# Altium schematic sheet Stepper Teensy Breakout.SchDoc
size A4
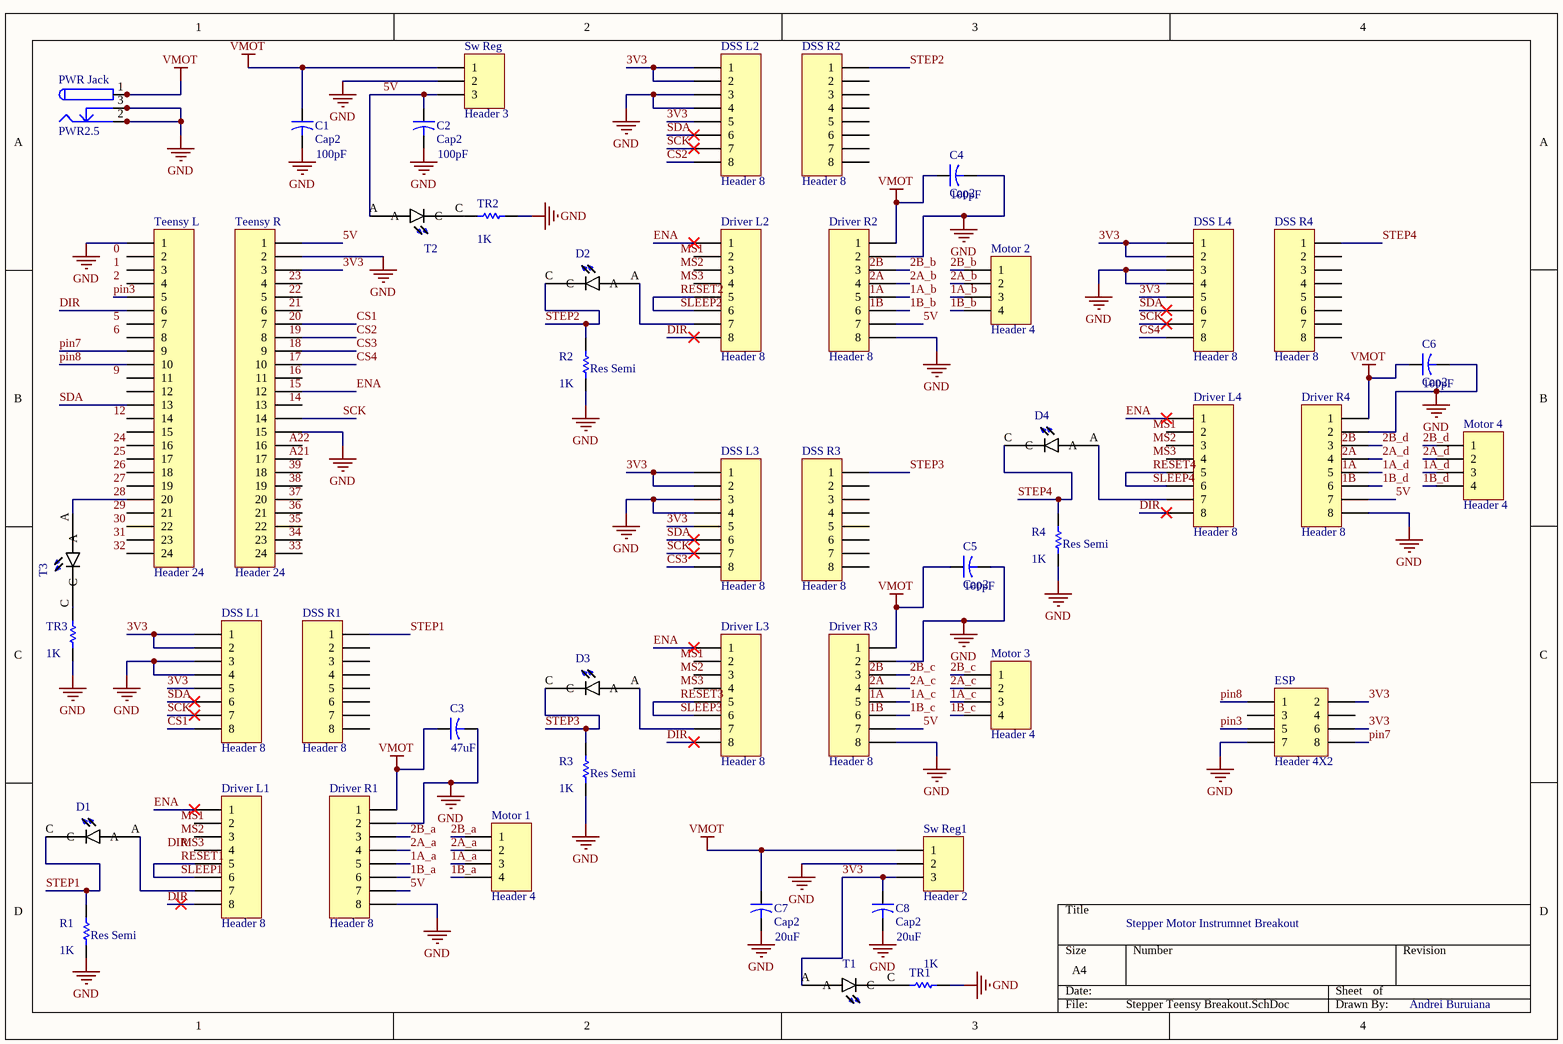
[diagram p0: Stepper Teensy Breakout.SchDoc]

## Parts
C1  Cap2  value 100pF  [CAPR5-4X5]
C2  Cap2  value 100pF  [CAPR5-4X5]
C3  value 47uF  [CAPR5-4X5]
C4  Cap2  value 100pF  [CAPR5-4X5]
C5  Cap2  value 100pF  [CAPR5-4X5]
C6  Cap2  value 100pF  [CAPR5-4X5]
C7  Cap2  value 20uF  [CAPR5-4X5]
C8  Cap2  value 20uF  [CAPR5-4X5]
D1  LTL-1CHYE  [LED_LTL-1CHYE_LTL-1CHYE(Primary)]  (value not drawn)
D2  LTL-1CHYE  [LED_LTL-1CHYE_LTL-1CHYE(Primary)]  (value not drawn)
D3  LTL-1CHYE  [LED_LTL-1CHYE_LTL-1CHYE(Primary)]  (value not drawn)
D4  LTL-1CHYE  [LED_LTL-1CHYE_LTL-1CHYE(Primary)]  (value not drawn)
Driver_L1  Header 8  [HDR1X8]
Driver_L2  Header 8  [HDR1X8]
Driver_L3  Header 8  [HDR1X8]
Driver_L4  Header 8  [HDR1X8]
Driver_R1  Header 8  [HDR1X8]
Driver_R2  Header 8  [HDR1X8]
Driver_R3  Header 8  [HDR1X8]
Driver_R4  Header 8  [HDR1X8]
DSS_L1  Header 8  [HDR1X8]
DSS_L2  Header 8  [HDR1X8]
DSS_L3  Header 8  [HDR1X8]
DSS_L4  Header 8  [HDR1X8]
DSS_R1  Header 8  [HDR1X8]
DSS_R2  Header 8  [HDR1X8]
DSS_R3  Header 8  [HDR1X8]
DSS_R4  Header 8  [HDR1X8]
ESP  Header 4X2  [HDR2X4]
Motor_1  Header 4  [HDR1X4]
Motor_2  Header 4  [HDR1X4]
Motor_3  Header 4  [HDR1X4]
Motor_4  Header 4  [HDR1X4]
PWR_Jack  PWR2.5  [KLD-0202]
R1  Res Semi  value 1K  [AXIAL-0.5]
R2  Res Semi  value 1K  [AXIAL-0.5]
R3  Res Semi  value 1K  [AXIAL-0.5]
R4  Res Semi  value 1K  [AXIAL-0.5]
Sw_Reg  Header 3  [HDR1X3]
Sw_Reg1  Header 2  [HDR1X3]
T1  LTL-1CHYE  [LED_LTL-1CHYE_LTL-1CHYE(Primary)]  (value not drawn)
T2  LTL-1CHYE  [LED_LTL-1CHYE_LTL-1CHYE(Primary)]  (value not drawn)
T3  LTL-1CHYE  [LED_LTL-1CHYE_LTL-1CHYE(Primary)]  (value not drawn)
Teensy_L  Header 24  [HDR1X24]
Teensy_R  Header 24  [HDR1X24]
TR1  value 1K  [AXIAL-0.5]
TR2  value 1K  [AXIAL-0.5]
TR3  value 1K  [AXIAL-0.5]

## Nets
GND: C1.2 C2.2 C3.2 C4.2 C5.2 C6.2 C7.2 C8.2 Driver_R1.2 Driver_R1.8 Driver_R2.2 Driver_R2.8 Driver_R3.2 Driver_R3.8 Driver_R4.2 Driver_R4.8 DSS_L1.3 DSS_L1.4 DSS_L2.3 DSS_L2.4 DSS_L3.3 DSS_L3.4 DSS_L4.3 DSS_L4.4 ESP.7 PWR_Jack.2 PWR_Jack.2A PWR_Jack.2B PWR_Jack.3 PWR_Jack.3A PWR_Jack.3B R1.1 R2.1 R3.1 R4.1 Sw_Reg.2 Sw_Reg1.2 Teensy_L.1 Teensy_R.2 Teensy_R.15 TR1.1 TR2.1 TR3.1
VMOT: C1.1 C3.1 C4.1 C5.1 C6.1 C7.1 Driver_R1.1 Driver_R2.1 Driver_R3.1 Driver_R4.1 PWR_Jack.1 PWR_Jack.1A PWR_Jack.1B Sw_Reg.1 Sw_Reg1.1
1A_a: Driver_R1.5 Motor_1.3
1A_b: Driver_R2.5 Motor_2.3
1A_c: Driver_R3.5 Motor_3.3
1A_d: Driver_R4.5 Motor_4.3
1B_a: Driver_R1.6 Motor_1.4
1B_b: Driver_R2.6 Motor_2.4
1B_c: Driver_R3.6 Motor_3.4
1B_d: Driver_R4.6 Motor_4.4
2A_a: Driver_R1.4 Motor_1.2
2A_b: Driver_R2.4 Motor_2.2
2A_c: Driver_R3.4 Motor_3.2
2A_d: Driver_R4.4 Motor_4.2
2B_a: Driver_R1.3 Motor_1.1
2B_b: Driver_R2.3 Motor_2.1
2B_c: Driver_R3.3 Motor_3.1
2B_d: Driver_R4.3 Motor_4.1
3V3: C8.1 DSS_L1.1 DSS_L1.2 DSS_L1.5 DSS_L2.1 DSS_L2.2 DSS_L2.5 DSS_L3.1 DSS_L3.2 DSS_L3.5 DSS_L4.1 DSS_L4.2 DSS_L4.5 ESP.2 ESP.6 Sw_Reg1.3 T1.A Teensy_R.3
5V: C2.1 Driver_R1.7 Driver_R2.7 Driver_R3.7 Driver_R4.7 Sw_Reg.3 T2.A Teensy_R.1
28: T3.A Teensy_L.20
CS1: DSS_L1.8 Teensy_R.7
CS2: DSS_L2.8 Teensy_R.8
CS3: DSS_L3.8 Teensy_R.9
CS4: DSS_L4.8 Teensy_R.10
DIR: Driver_L1.8 Driver_L2.8 Driver_L3.8 Driver_L4.8 Teensy_L.6
ENA: Driver_L1.1 Driver_L2.1 Driver_L3.1 Driver_L4.1 Teensy_R.12
pin3: ESP.5 Teensy_L.5
pin7: ESP.8 Teensy_L.9
pin8: ESP.1 Teensy_L.10
RESET1: Driver_L1.5 Driver_L1.6  [also labelled SLEEP1]
RESET2: Driver_L2.5 Driver_L2.6  [also labelled SLEEP2]
RESET3: Driver_L3.5 Driver_L3.6  [also labelled SLEEP3]
RESET4: Driver_L4.5 Driver_L4.6  [also labelled SLEEP4]
SCK: DSS_L1.7 DSS_L2.7 DSS_L3.7 DSS_L4.7 Teensy_R.14
SDA: DSS_L1.6 DSS_L2.6 DSS_L3.6 DSS_L4.6 Teensy_L.13
STEP1: D1.C DSS_R1.1 R1.2
STEP2: D2.C DSS_R2.1 R2.2
STEP3: D3.C DSS_R3.1 R3.2
STEP4: D4.C DSS_R4.1 R4.2
NetD1_A: D1.A Driver_L1.7
NetD2_A: D2.A Driver_L2.7
NetD3_A: D3.A Driver_L3.7
NetD4_A: D4.A Driver_L4.7
NetT1_C: T1.C TR1.2
NetT2_C: T2.C TR2.2
NetT3_C: T3.C TR3.2

Not connected (* = marked no-connect by the designer): Driver_L1 2 3 4; Driver_L2 2 3 4; Driver_L3 2 3 4; Driver_L4 2 3 4; DSS_R1 2 3 4 5 6 7 8; DSS_R2 2 3 4 5 6 7 8; DSS_R3 2 3 4 5 6 7 8; DSS_R4 2 3 4 5 6 7 8; ESP 3 4; Teensy_L 2 3 4 7 8 11 12 14 15 16 17 18 19 21 22 23 24; Teensy_R 4 5 6 11 13 16 17 18 19 20 21 22 23 24

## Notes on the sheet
- Stepper Motor Instrumnet Breakout
- Andrei Buruiana
- Labels drawn without touching a wire or pin: 0, 1, 1A, 1B, 2, 2A, 2B, 5, 6, 9, 12, 14, 15, 16, 17, 18, 19, 20, 21, 22, 23, 24, 25, 26, 27, 29, 30, 31, 32, 33, 34, 35, 36, 37, 38, 39, A21, A22, DIR, MS1, MS2, MS3

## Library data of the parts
C1-C8 = Cap2: Capacitor
D1-D4 T1-T3 = LTL-1CHYE: Yellow 3.1 mm 45Â° Tinted Clear 40 mcd 2.1 V LED Through Hole; MF: Lite-On
Driver_L1-Driver_L4 Driver_R1-Driver_R4 DSS_L1-DSS_L4 DSS_R1-DSS_R4 = Header 8: Header, 8-Pin
ESP = Header 4X2: Header, 4-Pin, Dual row
Motor_1-Motor_4 = Header 4: Header, 4-Pin
PWR_Jack = PWR2.5: Low Voltage Power Supply Connector
R1-R4 TR1-TR3 = Res Semi: Semiconductor Resistor
Sw_Reg Sw_Reg1 = Header 3: Header, 3-Pin
Teensy_L Teensy_R = Header 24: Header, 24-Pin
